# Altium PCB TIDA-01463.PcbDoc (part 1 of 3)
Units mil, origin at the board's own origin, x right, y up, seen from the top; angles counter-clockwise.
Board outline 6100 x 1060 mil, 4 copper layers (Top Layer, Signal Layer 1, Signal Layer 2, Bottom Layer), stack 61.2 mil thick; 209 components, 128 nets, 660 pads, 266 vias.
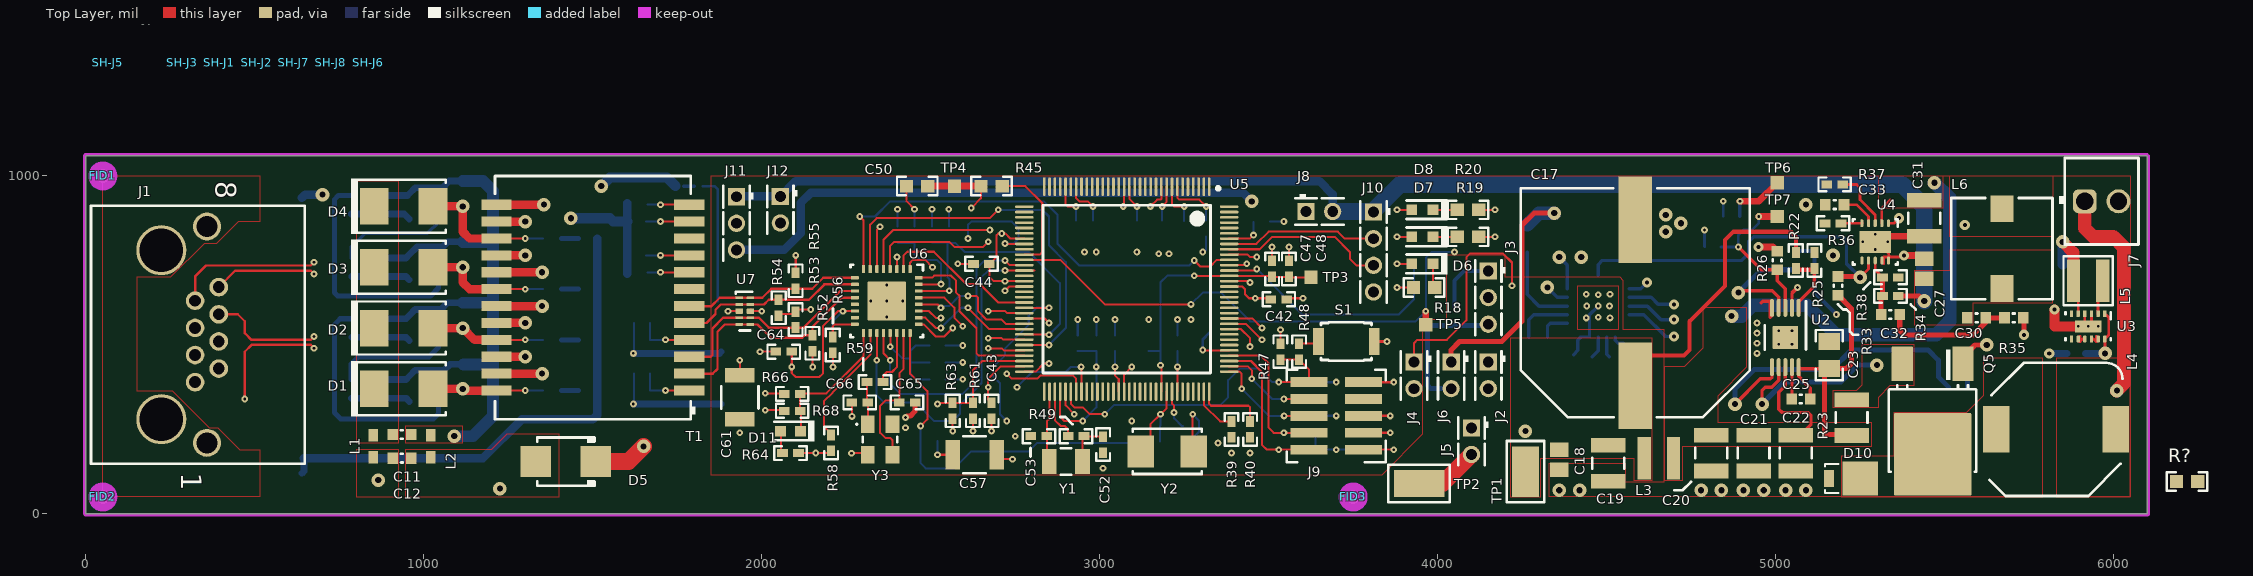
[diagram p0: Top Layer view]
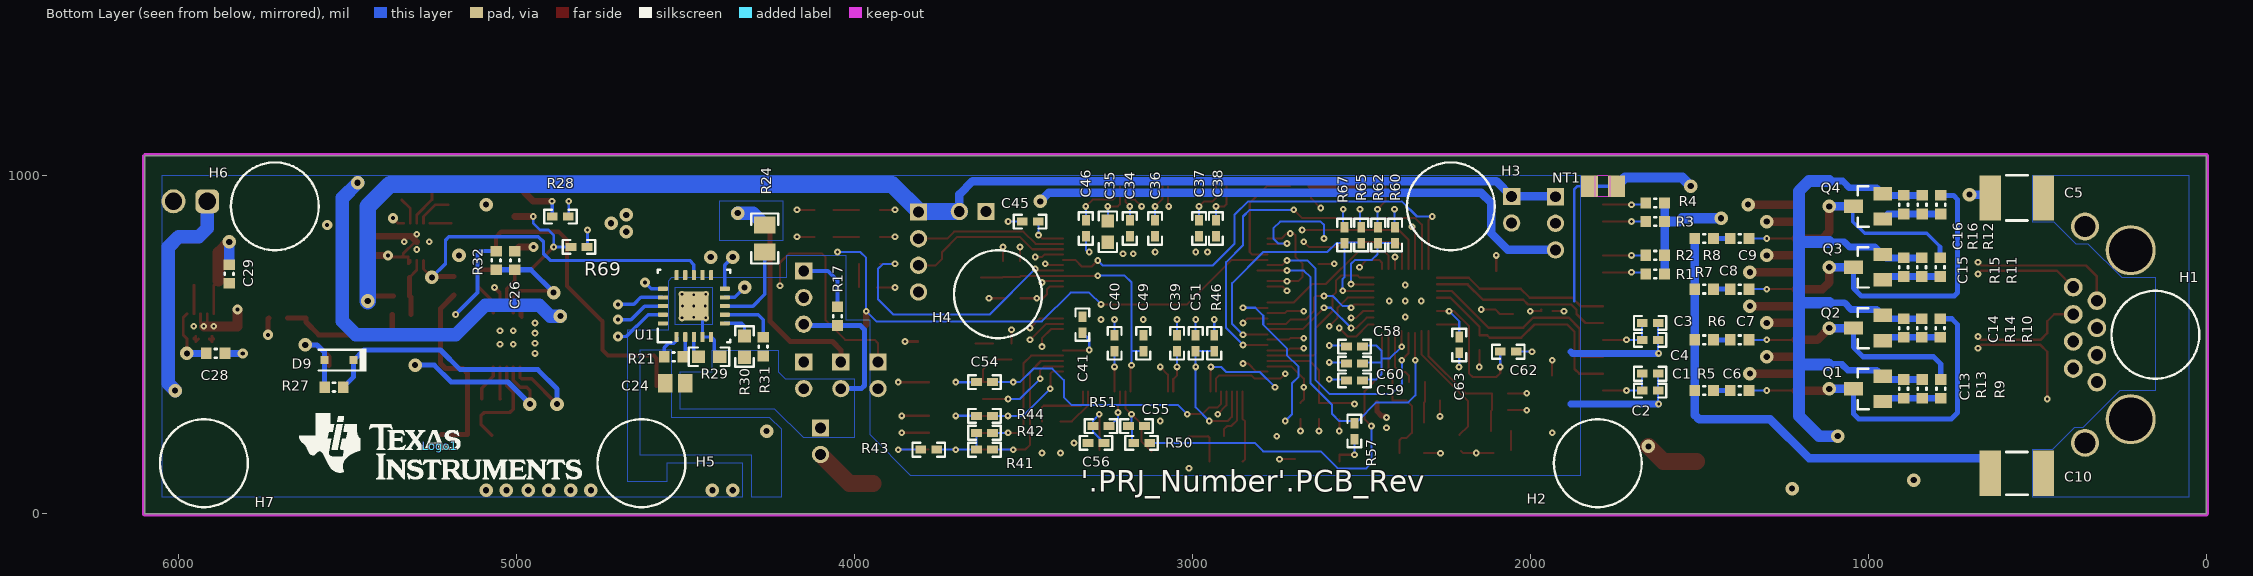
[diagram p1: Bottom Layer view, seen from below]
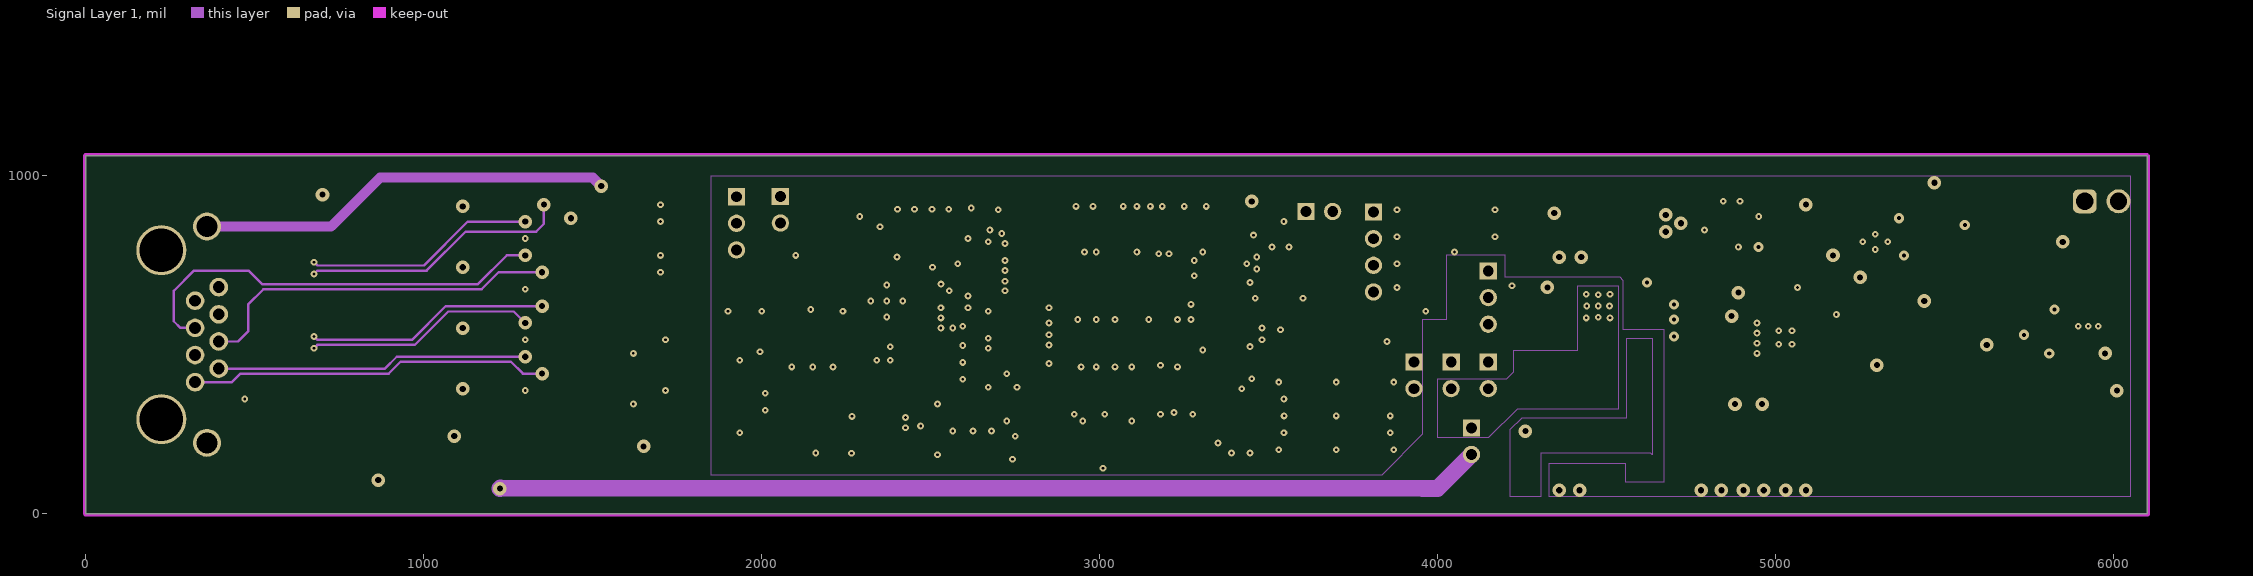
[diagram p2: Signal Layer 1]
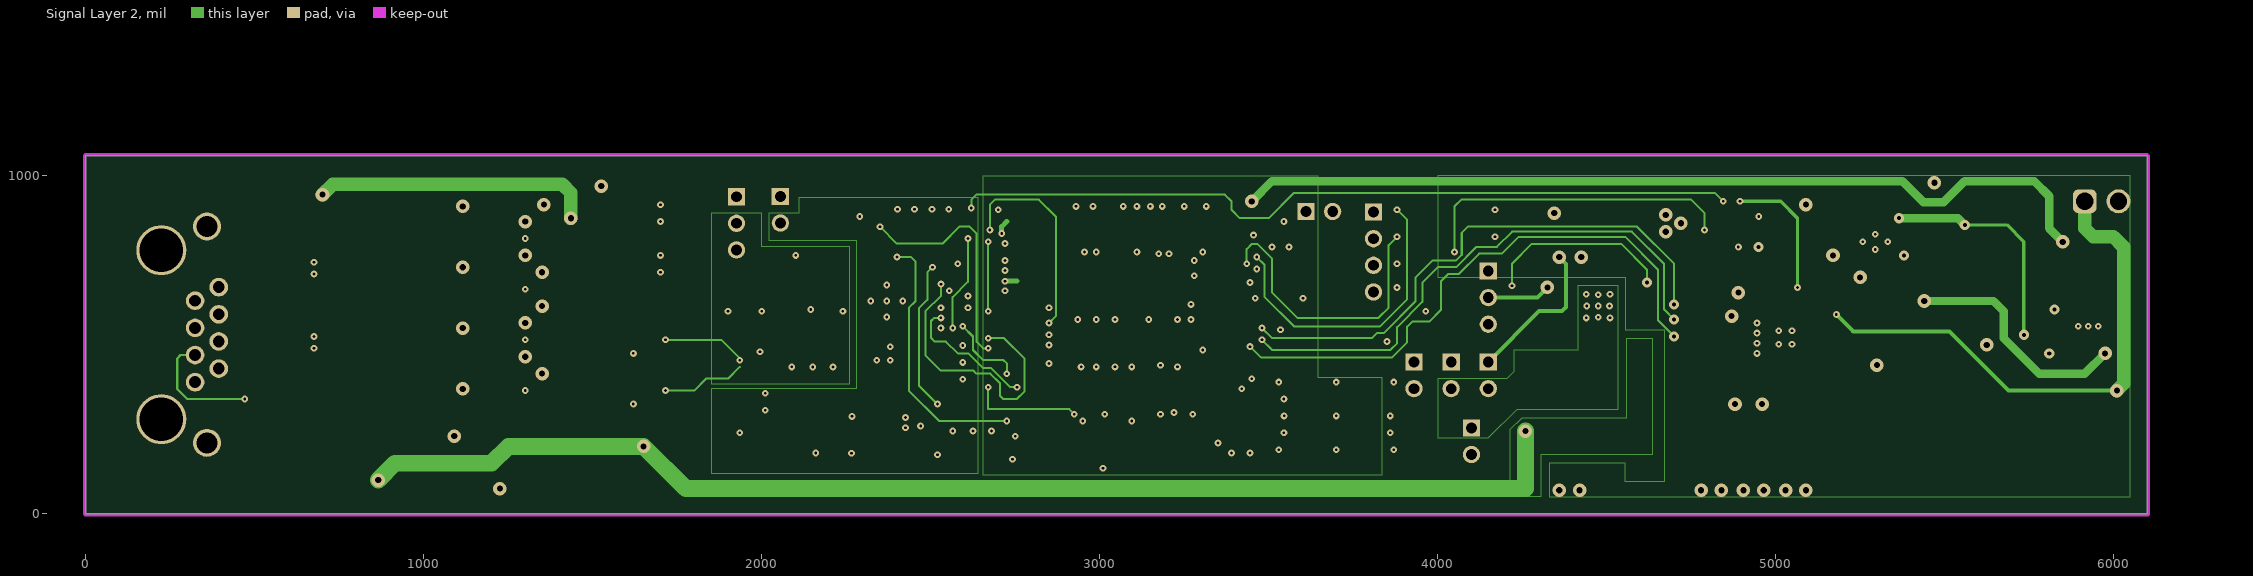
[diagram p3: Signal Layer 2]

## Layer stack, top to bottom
Top Solder: solder mask 0.4, Solder Resist, Dk 3.5
Top Layer: signal copper 1.4
Dielectric 1: core 15, FR-4, Dk 4.2
Signal Layer 1: signal copper 2.8
Dielectric 3: prepreg 22.8, Dk 4.2
Signal Layer 2: signal copper 2.8
Dielectric 2: core 15, FR-4, Dk 4.2
Bottom Layer: signal copper 1.4
Bottom Solder: solder mask 0.4, Solder Resist, Dk 3.5

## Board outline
0,0 6100,0 6100,1060 0,1060

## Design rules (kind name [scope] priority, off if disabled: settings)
AcuteAngle [All] p1: minimum=4.50000000000000E+0001 checktracksonly=FALSE
AssemblyTestPointUsage [All] p1: valid=2
BoardOutlineClearance BoardOutlineClearance_MountingHoles [OnCopper and InComponentClass('Mounting Holes')] p1: gap=40 ignorepadtopadclearanceinfootprint=FALSE
BoardOutlineClearance BoardOutlineClearance_Poly [OnCopper and IsPoly] p2: gap=25 ignorepadtopadclearanceinfootprint=FALSE
BoardOutlineClearance [OnCopper and Not InComponentClass('Logo') and not InComponentClass('FiducialMark') and not InRegion(1000,500,4000,800) and not InPoly] p3: gap=45 ignorepadtopadclearanceinfootprint=FALSE
Clearance Clearance_2 [InNamedPolygon('TOP_LAYER_NONET_P060')] p1: gap=60 ignorepadtopadclearanceinfootprint=FALSE except(0: Arc-Hole Track-Hole SMDPad-Hole THPad-Hole Via-Hole Fill-Hole Poly-Hole Region-Hole Text-Hole)
Clearance Clearance_1 [InNamedPolygon('BOTTOM_LAYER_NONET_P062')] p2: gap=60 ignorepadtopadclearanceinfootprint=FALSE except(0: Arc-Hole Track-Hole SMDPad-Hole THPad-Hole Via-Hole Fill-Hole Poly-Hole Region-Hole Text-Hole)
Clearance Clearance_Pwr2GndVia [(IsVia AND (InNet('GND') OR InNet('VCC_3P3'))) vs (IsVia AND (InNet('GND') OR InNet('VCC_3P3')))] p3: gap=5 ignorepadtopadclearanceinfootprint=FALSE except(0: Arc-Hole Track-Hole SMDPad-Hole THPad-Hole Via-Hole Fill-Hole Poly-Hole Region-Hole Text-Hole)
Clearance Clearance_Keepouts [((IsTrack Or IsArc) And Not InPoly) And IsFree and IsKeepOut vs ((IsTrack Or IsArc) And Not InPoly) And IsFree and IsKeepOut] p4: gap=0 ignorepadtopadclearanceinfootprint=FALSE
Clearance Clearance_Poly [InPolygon] p5: gap=20 ignorepadtopadclearanceinfootprint=FALSE except(0: Arc-Hole Track-Hole SMDPad-Hole THPad-Hole Via-Hole Fill-Hole Poly-Hole Region-Hole Text-Hole)
Clearance [All] p6: gap=5 ignorepadtopadclearanceinfootprint=FALSE except(0: Arc-Hole Track-Hole SMDPad-Hole THPad-Hole Via-Hole Fill-Hole Poly-Hole Region-Hole Text-Hole)
ComponentClearance ComponentClearance_MountingHoles_FiducialMarks [InComponentClass('Mounting Holes') vs InComponentClass('FiducialMark')] p1: gap=50 collisioncheckmode=3 verticalgap=10 showdistances=FALSE
ComponentClearance ComponentClearance_Shunt [InComponentClass('Header') vs InComponentClass('Shunt')] p2: gap=0 collisioncheckmode=3 verticalgap=0 showdistances=FALSE
ComponentClearance ComponentClearance_Logo [InComponentClass('Logo')] p3: gap=50 collisioncheckmode=3 verticalgap=10 showdistances=FALSE
ComponentClearance ComponentClearance_ScrewToNut [(HasFootprint('NY PMS 440 0025 PH')) vs (HasFootprint('Keystone_1902C'))] p4: gap=5 collisioncheckmode=3 verticalgap=10 showdistances=FALSE
ComponentClearance ComponentClearance_MountingHoles [InComponentClass('Mounting Holes')] p5: gap=250 collisioncheckmode=3 verticalgap=100000 showdistances=FALSE
ComponentClearance ComponentClearance_SmallPassives [HasFootprint('0201*') or HasFootprint('0402*') or HasFootprint('0508') or HasFootprint('0603*') or HasFootprint('0612') or HasFootprint('0805*') or HasFootprint('0815*') or HasFootprint('0830*') or HasFootprint('1206*') or HasFootprint('1210*') or HasFootprint('1808*') or HasFootprint('1812*') or HasFootprint('1825*') or HasFootprint('2010*') or HasFootprint('2220*') or HasFootprint('2225*') or HasFootprint('2512*') or HasFootprint('2728*') or HasFootprint('3518*') vs HasFootprint('0201*') or HasFootprint('0402*') or HasFootprint('0508') or HasFootprint('0603*') or HasFootprint('0612') or HasFootprint('0805*') or HasFootprint('0815*') or HasFootprint('0830*') or HasFootprint('1206*') or HasFootprint('1210*') or HasFootprint('1808*') or HasFootprint('1812*') or HasFootprint('1825*') or HasFootprint('2010*') or HasFootprint('2220*') or HasFootprint('2225*') or HasFootprint('2512*') or HasFootprint('2728*') or HasFootprint('3518*')] p6: gap=14.96 collisioncheckmode=3 verticalgap=10 showdistances=FALSE
ComponentClearance ComponentClearance_THtoSMT [IsThruComponent vs IsSMTComponent] p7: gap=40 collisioncheckmode=3 verticalgap=30 showdistances=FALSE
ComponentClearance ComponentClearance_THtoTH [IsThruComponent vs IsThruComponent] p8: gap=30 collisioncheckmode=3 verticalgap=30 showdistances=FALSE
ComponentClearance [All] p9: gap=30 collisioncheckmode=3 verticalgap=10 showdistances=FALSE
DiffPairsRouting [(InNet('TXD_N') OR InNet('TXD_P') OR InNet('TXDC_P') OR InNet('TXDC_N') OR InNet('RXD_N') OR InNet('RXD_P') OR InNet('RXDC_P') OR InNet('RXDC_N'))] p1: maxlimit=50 minlimit=5 mostfreqgap=5 toplayer_minwidth=6 toplayer_maxwidth=14 toplayer_prefwidth=11 midlayer1_minwidth=6 midlayer1_maxwidth=14 midlayer1_prefwidth=11 midlayer2_minwidth=6 midlayer2_maxwidth=14 midlayer2_prefwidth=11 bottomlayer_minwidth=6 bottomlayer_maxwidth=14 bottomlayer_prefwidth=11 maxuncoupledlength=1000
FabricationTestPointUsage TestPointUsage [All] p1: valid=2 allowmultiple=FALSE
FabricationTestpoint Testpoint [All] p1: side=3 testpointundercomponent=TRUE minsize=40 maxsize=100 preferedsize=60 minholesize=0 maxholesize=40 preferedholesize=32 testpointgrid=1 allowsidetop=TRUE allowsidebottom=TRUE usegrid=TRUE gridtolerance=0.01
FanoutControl Fanout_LCC [IsLCC] p1: bgadir=Out bgaviamode=Centered fanoutstyle=Auto fanoutdirection=Alternating viagrid=1 // Fanout_LCC (Default Rule)
FanoutControl Fanout_BGA [IsBGA] p2: bgadir=Out bgaviamode=Centered fanoutstyle=Auto fanoutdirection=Alternating viagrid=1 // Fanout_BGA (Default Rule)
FanoutControl Fanout_Default [All] p4: bgadir=Out bgaviamode=Centered fanoutstyle=Auto fanoutdirection=Alternating viagrid=1 // Fanout_Default (Default Rule)
FanoutControl Fanout_Small [(CompPinCount < 5)] p5: bgadir=Out bgaviamode=Centered fanoutstyle=Auto fanoutdirection=OutThenIn viagrid=1 // Fanout_Small (Default Rule)
HoleSize [All] p1: absolutevalues=TRUE maxlimit=251 minlimit=7.87 maxpercent=80.000 minpercent=20.000
MinimumAnnularRing MinimumAnnularRing_ThermalPadVias [IsVia and InAnyComponent] p1: minimumring=5
MinimumAnnularRing [All] p2: minimumring=5
MinimumSolderMaskSliver MinimumSolderMaskSliver_Logo [InComponentClass('Logo') vs InComponentClass('Logo')] p1: minsoldermaskwidth=0.7
MinimumSolderMaskSliver [All] p2: minsoldermaskwidth=3.94
PlaneConnect [All] p1: planeconnectstyle=Relief reliefexpansion=13 reliefentries=4 reliefconductorwidth=10 reliefairgap=10
PolygonConnect [All] p1: connectstyle=Direct reliefconductorwidth=10 reliefentries=4 polygonreliefangle="90 Angle" airgapwidth=10
RoutingVias ThermalPadVias [IsVia and InAnyComponent] p1: holewidth=7.87 width=19.68 viastyle="Through Hole" minholewidth=7.87 minwidth=19.68 maxholewidth=12.99 maxwidth=23.62
RoutingVias [All] p2: holewidth=8 width=20 viastyle="Through Hole" minholewidth=8 minwidth=20 maxholewidth=20 maxwidth=40
SMDNeckDown [All] p1: percent=100.000
SilkToBoardRegionClearance [Not ((IsComment or IsDesignator) And (Hide <> 'False')) and not InRegion(1000,500,4000,800)] p1:
SilkToSilkClearance SilkToSilkClearance_Pb-FreeLogo [(HasFootprint('Pb-Free_Overlay_Medium') OR HasFootprint('Pb-Free_Overlay_Small')) vs (HasFootprint('Pb-Free_Overlay_Medium') OR HasFootprint('Pb-Free_Overlay_Small'))] p1: silktosilkclearance=0
SilkToSilkClearance [All] p2: silktosilkclearance=4
SilkToSolderMaskClearance SilkToComponentPadClearance [IsPad and InAnycomponent] p1: minsilkscreentomaskgap=5 clearancetoexposedcopper=TRUE
SilkToSolderMaskClearance "Silk to Solder Mask Opening" [All] p2: minsilkscreentomaskgap=4 clearancetoexposedcopper=FALSE
SolderMaskExpansion SolderMaskExpansion_1 [All] p1: expansion=0.05
SolderMaskExpansion [All] p2: expansion=0.05
Width WidthRoom [TouchesRoom('RoomU1') OR  TouchesRoom('RoomU2')] p1: maxlimit=10 minlimit=6 preferedwidth=6
Width [All] p2: maxlimit=50 minlimit=6 preferedwidth=15 checkconnectedcopper=TRUE
15 further rules are at their usual default settings.

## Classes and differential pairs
component class Shunt: SH-J1 SH-J2 SH-J3 SH-J4 SH-J5 SH-J6 SH-J7 SH-J8
component class PMP20537_RevB_SH4: C57 C58 C59 C60 C61 C62 C63 C64 C65 C66 D11 J11 J12 R52 R53 R54 R55 R56 R57 R58 R59 R60 R61 R62 R63 R64 R65 R66 R67 R68 R71 R77 SH-J7 SH-J8 U6 U7 Y3
component class PMP20537_RevB_SH2: C17 C18 C19 C20 C21 C22 C23 C24 C25 C26 C27 C28 C29 C30 C31 C32 C33 D6 D7 D8 D9 D10 J2 J3 J4 J5 J6 J7 L3 L4 L5 L6 Q5 R17 R18 R19 R20 R21 R22 R23 R24 R25 R26 R27 R28 R29 R30 R31 R32 R33 R34 R35 R36 R37 R38 R69 R? SH-J1 SH-J2 SH-J3 SH-J4 SH-J5 TP1 TP2 TP6 TP7 U1 U2 U3 U4
component class PMP20537_RevB_SH1: C1 C2 C3 C4 C5 C6 C7 C8 C9 C10 C11 C12 C13 C14 C15 C16 D1 D2 D3 D4 D5 J1 L1 L2 NT1 Q1 Q2 Q3 Q4 R1 R2 R3 R4 R5 R6 R7 R8 R9 R10 R11 R12 R13 R14 R15 R16 T1
component class PMP20537_RevB_EVM_Hardware: !PCB1 FID1 FID2 FID3 H1 H2 H3 H4 H5 H6 H7 Logo1
component class PMP20537_RevB_SH3: C34 C35 C36 C37 C38 C39 C40 C41 C42 C43 C44 C45 C46 C47 C48 C49 C50 C51 C52 C53 C54 C55 C56 J8 J9 J10 R39 R40 R41 R42 R43 R44 R45 R46 R47 R48 R49 R50 R51 S1 SH-J6 TP3 TP4 TP5 U5 Y1 Y2
component class Header: J2 J3 J4 J5 J6 J8 J9 J10 J11 J12
component class Logo: Logo1
component class FiducialMark: FID1 FID2 FID3
differential pair TXD: +TXD_P -TXD_N
differential pair RXD: +RXD_P -RXD_N

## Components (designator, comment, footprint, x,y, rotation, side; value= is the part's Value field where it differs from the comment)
C1 "C1005X5R1A105K050BB" 0402 1645,415 r180 bottom value=1uF
C2 "885012205037" 0402 1645,365 r180 bottom value=0.1uF
C3 "C1005X5R1A105K050BB" 0402 1645,565 r180 bottom value=1uF
C4 "885012205037" 0402 1645,515 r180 bottom value=0.1uF
C5 "1812GC472KAT1A" 1812_254 560,935 r0 bottom value=4700pF
C6 "GRM188R72A103KA01D" 0603L 1380,365 r0 bottom value=0.01uF
C7 "GRM188R72A103KA01D" 0603L 1380,515 r0 bottom value=0.01uF
C8 "GRM188R72A103KA01D" 0603L 1380,665 r0 bottom value=0.01uF
C9 "GRM188R72A103KA01D" 0603L 1380,815 r0 bottom value=0.01uF
C10 "GR443QR73D102KW01L" 1812 560,120 r180 bottom value=1000pF
C11 "C1608X7R2A102K080AA" 0603L 935,235 r0 top value=1000pF
C12 "C1608X7R2A102K080AA" 0603L 935,165 r0 top value=1000pF
C13 "885012006060" 0603L 895,370 r90 bottom value=330pF
C14 "885012006060" 0603L 895,550 r90 bottom value=330pF
C15 "885012006060" 0603L 895,730 r90 bottom value=330pF
C16 "885012006060" 0603L 895,915 r90 bottom value=330pF
C17 "EEV-FK2A101M" SM_RADIAL_J16 4585,625 r90 top value=100uF
C18 "C0805C104K1RACTU" 0805L 4360,160 r270 top value=0.1uF
C19 "C1210C225K1RACTU" 1210_210L 4505,150 r270 top value=2.2uF
C20 "C1210C225K1RACTU" 1210_210L 4810,180 r270 top value=2.2uF
C21 "C1210C225K1RACTU" 1210_210L 4935,180 r270 top value=2.2uF
C22 "C1210C225K1RACTU" 1210_210L 5060,180 r270 top value=2.2uF
C23 "C0805C104K1RACTU" 0805_HV 5158.98,470 r90 top value=0.1uF
C24 "C0805C104K1RACTU" 0805L 4530,386.42 r180 bottom value=0.1uF
C25 "885012206052" 0603L 5075,340 r180 top value=1uF
C26 "06035A471JAT2A" 0603L 5005,750 r90 bottom value=470pF
C27 "GRM21BR60J226ME39L" 0805L 5440,725 r90 top value=22uF
C28 "GRM188R60J106ME47D" 0603L 5890,475 r180 bottom value=10uF
C29 "GRM188R60J106ME47D" 0603L 5850,710 r270 bottom value=10uF
C30 "885012206036" 0603L 5595,580 r0 top value=2200pF
C31 "C1210C225K1RACTU" 1210_210L 5440,875 r270 top value=2.2uF
C32 "885012206040" 0603L 5340,590 r180 top value=0.01uF
C33 "885012206091" 0603L 5175,915 r180 top value=0.022uF
C34 "C1005X5R1A105K050BB" 0402 3185,845 r270 bottom value=1uF
C35 "885012206048" 0603 3250,835 r270 bottom value=0.22uF
C36 "885012205037" 0402 3110,845 r270 bottom value=0.1uF
C37 "885012205037" 0402 2980,845 r270 bottom value=0.1uF
C38 "885012205037" 0402 2930,845 r270 bottom value=0.1uF
C39 "885012205037" 0402 3045,505 r90 bottom value=0.1uF
C40 "885012205037" 0402 3230,505 r90 bottom value=0.1uF
C41 "885012205037" 0402 3325,560 r90 bottom value=0.1uF
C42 "885012205037" 0402 3530,635 r0 top value=0.1uF
C43 "885012205037" 0402 2680,305 r270 top value=0.1uF
C44 "885012205037" 0402 2650,740 r180 top value=0.1uF
C45 "885012205037" 0402 3480,865 r0 bottom value=0.1uF
C46 "885012205031" 0402 3315,845 r270 bottom value=0.01uF
C47 "885012105013" 0402 3510,725 r90 top value=2.2uF
C48 "C1005X5R1A105K050BB" 0402 3560,725 r90 top value=1uF
C49 "885012205037" 0402 3145,505 r90 bottom value=0.1uF
C50 "885012206046" 0603 2460,970 r180 top value=0.1uF
C51 "885012205037" 0402 2990,505 r90 bottom value=0.1uF
C52 "GRM1555C1H180JA01D" 0402 3010,205 r270 top value=18pF
C53 "GRM1555C1H180JA01D" 0402 2820,230 r180 top value=18pF
C54 "885012205037" 0402 3615,390 r0 bottom value=0.1uF
C55 "GRM1555C1H220JA01D" 0402 3165,260 r180 bottom value=22pF
C56 "GRM1555C1H220JA01D" 0402 3285,210 r0 bottom value=22pF
C57 "CGA6P1X7R1E106M250AC" 1210_280 2630,175 r0 top value=10uF
C58 "885012205031" 0402 2520,495 r0 bottom value=0.01uF
C59 "885012205061" 0402 2520,395 r0 bottom value=1000pF
C60 "885012005061" 0402 2520,445 r0 bottom value=100pF
C61 "CGA6P1X7R1E106M250AC" 1210_280 1935,345 r270 top value=10uF
C62 "885012205031" 0402 2065,480 r180 bottom value=0.01uF
C63 "885012205061" 0402 2210,500 r270 bottom value=1000pF
C64 "885012005061" 0402 2065,480 r180 top value=100pF
C65 "C0402C120J3GACAUTO" 0402 2430,330 r0 top value=12pF
C66 "C0402C120J3GACAUTO" 0402 2290,330 r180 top value=12pF
D1 "B2100-13-F" SMB 940,370 r0 top value=100V
D2 "B2100-13-F" SMB 940,550 r0 top value=100V
D3 "B2100-13-F" SMB 940,730 r0 top value=100V
D4 "B2100-13-F" SMB 940,910 r0 top value=100V
D5 "824520581" DO214-AA-600W_UNI 1420,155 r180 top value=58V
D6 "150060YS75000" WL-SMCW_YELLOW 3955,740 r180 top value=Yellow
D7 "150060YS75000" WL-SMCW_YELLOW 3955,820 r180 top value=Yellow
D8 "150060YS75000" WL-SMCW_YELLOW 3955,900 r180 top value=Yellow
D9 "SD107WS-7-F" sod-323 5525,455 r0 bottom value=30V
D10 "SS2PH10-M3" DO-220AA 5205,105 r180 top value=100V
D11 "19-21UYC/S530-A4/TR8" 19-21_Yellow 2085,245 r180 top value=Yellow
FID1 "Fiducial" Fiducial10-20 50,1000 r0 top
FID2 "Fiducial" Fiducial10-20 50,50 r0 top
FID3 "Fiducial" Fiducial10-20 3750,50 r0 top
H1 "SJ5382" 3M_SJ5382 150,530 r180 bottom
H2 "SJ5382" 3M_SJ5382 1800,150 r180 bottom
H3 "SJ5382" 3M_SJ5382 2235,910 r180 bottom
H4 "SJ5382" 3M_SJ5382 3575,650 r180 bottom
H5 "SJ5382" 3M_SJ5382 4630,150 r180 bottom
H6 "SJ5382" 3M_SJ5382 5715,910 r180 bottom
H7 "SJ5382" 3M_SJ5382 5925,150 r180 bottom
J1 "1-406541-1" TEC_1-406541-1 330,530 r270 top
J2 "PTT-102-01-L-S" Samtec_PTT-102-01-x-S 4150,410 r270 top
J3 "PTT-103-01-L-S" Samtec_PTT-103-01-x-S 4150,640 r270 top
J4 "PTT-102-01-L-S" Samtec_PTT-102-01-x-S 3930,410 r270 top
J5 "PTT-102-01-L-S" Samtec_PTT-102-01-x-S 4100,215 r270 top
J6 "PTT-102-01-L-S" Samtec_PTT-102-01-x-S 4040,410 r270 top
J7 "691210910002" Wurth_691210910002 5965,925 r0 top
J8 "PTT-102-01-L-S" Samtec_PTT-102-01-x-S 3650,895 r0 top
J9 "FTSH-105-01-F-DV" Samtec_FTSH-105-01-x-DV 3700,290 r180 top
J10 "PTT-104-01-L-S" Samtec_PTT-104-01-x-S 3810,775 r270 top
J11 "PTT-103-01-L-S" Samtec_PTT-103-01-x-S 1925,860 r270 top
J12 "PTT-102-01-L-S" Samtec_PTT-102-01-x-S 2055,900 r270 top
L1 "742792641" WE-CBF_0603 850,200 r270 top value="300 ohm"
L2 "742792641" WE-CBF_0603 1020,200 r270 top value="300 ohm"
L3 "744025003" WE-TPC_2828 4655,165 r0 top value=3.3uH
L4 "7447714330" WE-PD_1050 5830,250 r0 top value=33uH
L5 "744028002" WE-TPC-T 5925,690 r180 top value=2.2uH
L6 "7447779233" WE-PD_7345_PlasticBase 5670,785 r270 top value=330uH
Logo1 "Texas Instruments" TI_Stacked_Overlay_Small 5225,200 r180 bottom
NT1 "Net-Tie" Net-Tie_0805_HV_NoOverlay 1785,970 r0 bottom net-tie
Q1 "FDN8601" SSOT-3 1000,370 r90 bottom value=100V
Q2 "FDN8601" SSOT-3 1000,550 r90 bottom value=100V
Q3 "FDN8601" SSOT-3 1000,730 r90 bottom value=100V
Q4 "FDN8601" SSOT-3 1000,910 r90 bottom value=100V
Q5 "ZXMP10A16KTC" DPAK 5465,310 r270 top value=-100V
R1 "CRCW060375R0FKEA" 0603L 1630,710 r0 bottom value=75.0
R2 "CRCW060375R0FKEA" 0603L 1630,765 r0 bottom value=75.0
R3 "CRCW060375R0FKEA" 0603L 1630,865 r0 bottom value=75.0
R4 "CRCW060375R0FKEA" 0603L 1630,920 r0 bottom value=75.0
R5 "CRCW060375R0FKEA" 0603L 1485,365 r180 bottom value=75.0
R6 "CRCW060375R0FKEA" 0603L 1485,515 r180 bottom value=75.0
R7 "CRCW060375R0FKEA" 0603L 1485,665 r180 bottom value=75.0
R8 "CRCW060375R0FKEA" 0603L 1485,815 r180 bottom value=75.0
R9 "CRCW06031M00FKEA" 0603L 785,370 r90 bottom value=1.00Meg
R10 "CRCW06031M00FKEA" 0603L 786.69,550 r90 bottom value=1.00Meg
R11 "CRCW06031M00FKEA" 0603L 786.69,730 r90 bottom value=1.00Meg
R12 "CRCW06031M00FKEA" 0603L 785,915 r90 bottom value=1.00Meg
R13 "CRCW0603232KFKEA" 0603L 840,370 r270 bottom value=232k
R14 "CRCW0603232KFKEA" 0603L 841.69,550 r270 bottom value=232k
R15 "CRCW0603232KFKEA" 0603L 841.69,730 r270 bottom value=232k
R16 "CRCW0603232KFKEA" 0603L 840,915 r270 bottom value=232k
R17 "CRCW060353K6FKEA" 0603L 4050,585 r270 bottom value=53.6k
R18 "RC0603FR-071K3L" 0603 3960,670 r0 top value=1.30k
R19 "RC0603FR-071K3L" 0603 4090,820 r180 top value=1.30k
R20 "RC0603FR-071K3L" 0603 4090,900 r180 top value=1.30k
R21 "CRCW060327K4FKEA" 0603L 4535,465 r0 bottom value=27.4k
R22 "CRCW04021M00FKED" 0402 5060,750 r90 top value=1.00Meg
R23 "MCR25JZHFLR180" 1210L 5225,285 r270 top value=0.18
R24 "ERJ-6GEYJ132V" 0805_HV 4265,815 r270 bottom value=1.3k
R25 "CRCW0402100KFKED" 0402 5115,750 r270 top value=100k
R26 "CRCW060349K9FKEA" 0603L 5005,750 r270 top value=49.9k
R27 "CRCW06030000Z0EA" 0603L 5540,375 r0 bottom value=0
R28 "ERJ-2GE0R00X" 0402 4870,880 r0 bottom value=0
R29 "RC0603FR-0763R4L" 0603 4430,465 r0 bottom value=63.4
R30 "RC0603FR-07243RL" 0603 4325,495 r90 bottom value=243
R31 "CRCW060349K9FKEA" 0603L 4270,495 r270 bottom value=49.9k
R32 "CRCW060323K2FKEA" 0603L 5060,750 r270 bottom value=23.2k
R33 "CRCW060349K9FKEA" 0603L 5185,675 r270 top value=49.9k
R34 "CRCW040210K0FKED" 0402 5340,645 r0 top value=10.0k
R35 "CRCW0603301KFKEA" 0603L 5705,580 r180 top value=301k
R36 "CRCW0402105KFKED" 0402 5170,860 r0 top value=105k
R37 "CRCW040224K9FKED" 0402 5175,975 r0 top value=24.9k
R38 "CRCW04025K76FKED" 0402 5340,700 r180 top value=5.76k
R39 "CRCW040210K0FKED" 0402 3390,250 r270 top value=10.0k
R40 "CRCW040210K0FKED" 0402 3445,250 r270 top value=10.0k
R41 "CRCW040210K0FKED" 0402 3615,190 r0 bottom value=10.0k
R42 "CRCW040210K0FKED" 0402 3615,240 r0 bottom value=10.0k
R43 "ERJ-2RKF1000X" 0402 3780,190 r180 bottom value=100
R44 "CRCW040210K0FKED" 0402 3615,290 r180 bottom value=10.0k
R45 "CRCW06031K00FKEA" 0603 2680,970 r180 top value=1.00k
R46 "CRCW040249R9FKED" 0402 2935,505 r270 bottom value=49.9
R47 "CRCW040210K0FKED" 0402 3535,480 r90 top value=10.0k
R48 "ERJ-2RKF1000X" 0402 3590,480 r270 top value=100
R49 "ERJ-2GE0R00X" 0402 2930,230 r0 top value=0
R50 "ERJ-2GE0R00X" 0402 3150,210 r0 bottom value=0
R51 "ERJ-2GE0R00X" 0402 3270,260 r180 bottom value=0
R52 "CRCW040249R9FKED" 0402 2150,505 r270 top value=49.9
R53 "CRCW040249R9FKED" 0402 2100,575 r90 top value=49.9
R54 "CRCW040249R9FKED" 0402 2050,610 r270 top value=49.9
R55 "CRCW040249R9FKED" 0402 2100,690 r90 top value=49.9
R56 "CRCW04024K87FKED" 0402 2210,500 r270 top value=4.87k
R57 "CRCW04022K21FKED" 0402 2520,245 r90 bottom value=2.21k
R58 "CRCW04023K32FKED" 0402 2205,210 r270 top value=3.32k
R59 "ERJ-2GE0R00X" 0402 2335,390 r180 top value=0
R60 "CRCW040210K0FKED" 0402 2400,825 r90 bottom value=10.0k
R61 "CRCW040210K0FKED" 0402 2625,305 r270 top value=10.0k
R62 "CRCW04022K49FKED" 0402 2450,825 r270 bottom value=2.49k
R63 "CRCW04022K49FKED" 0402 2565,305 r90 top value=2.49k
R64 "CRCW0402332RFKED" 0402 2085,180 r180 top value=332
R65 "CRCW040210K0FKED" 0402 2500,825 r90 bottom value=10.0k
R66 "CRCW04022K49FKED" 0402 2090,355 r180 top value=2.49k
R67 "CRCW04022K49FKED" 0402 2550,825 r270 bottom value=2.49k
R68 "CRCW04022K49FKED" 0402 2090,305 r0 top value=2.49k
R69 "ERJ-2GE0R00X" 0402 4815,790 r0 bottom value=0
R? "RC0603FR-071K3L" 0603 6218,96 r0 top value=1.30k
S1 "SKRKAEE010" SW_SKRKAEE010 3730,510 r180 top
SH-J1 "2SN-BK-G" 2SN-BK-G 395,1335 r90 top value=1x2
SH-J2 "2SN-BK-G" 2SN-BK-G 505,1335 r90 top value=1x2
SH-J3 "2SN-BK-G" 2SN-BK-G 285,1335 r90 top value=1x2
SH-J4 "2SN-BK-G" 2SN-BK-G 175,1335 r90 top value=1x2
SH-J5 "2SN-BK-G" 2SN-BK-G 65,1335 r90 top value=1x2
SH-J6 "2SN-BK-G" 2SN-BK-G 835,1335 r90 top value=1x2
SH-J7 "2SN-BK-G" 2SN-BK-G 615,1335 r90 top value=1x2
SH-J8 "2SN-BK-G" 2SN-BK-G 725,1335 r90 top value=1x2
T1 "7490220122" Wurth_7490220122 1500,640 r180 top value="350 uH"
TP1 "TESTPOINT" Keystone_5019 4260,125 r270 top
TP2 "TESTPOINT" Keystone_5019 3945,90 r0 top
TP3 "TESTPOINT" PAD_1MM_SQUARE 3625,700 r0 top
TP4 "TESTPOINT" PAD_1MM_SQUARE 2570,970 r0 top
TP5 "TESTPOINT" PAD_1MM_SQUARE 3965,560 r90 top
TP6 "TESTPOINT" PAD_1MM_SQUARE 5005,980 r90 top
TP7 "TESTPOINT" PAD_1MM_SQUARE 5005,880 r90 top
U1 "TPS2372-4RGWR" RGW0020B 4475,615 r90 bottom
U2 "LM3409HVMYX/NOPB" MUC10A_N 5029,522 r270 top
U3 "TPS62740DSSR" DSS0012A 5925,555 r270 top
U4 "LM5165DRCR" DRC0010J 5295,805 r270 top
U5 "TM4C1292NCPDTI3R" PDT0128A 3080,665 r270 top
U6 "DP83822IRHBR" RHB0032B 2370,630 r270 top
U7 "TPD4E05U06QDQARQ1" DQA0010A 1950,600 r0 top
Y1 "ABS07-32.768KHZ-9-T" XTAL_ABS07 2900,155 r180 top
Y2 "NX5032GA-25.000M-STD-CSK-4" NDK_NX5032GA 3200,185 r0 top
Y3 "CX3225CA25000D0HSSCC" Kyocera_CX3225CA 2350,220 r0 top

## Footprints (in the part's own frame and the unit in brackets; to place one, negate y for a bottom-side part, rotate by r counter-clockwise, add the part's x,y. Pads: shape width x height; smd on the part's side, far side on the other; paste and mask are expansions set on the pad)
2SN-BK-G [mil] "Samtec STEP model"
  round 1 on Mech3: 0(0,0)
  body extent -78,-39 79,39, height 188
3M_SJ5382 [mil] "3M BUMPON"
  silkscreen extent -130,-130 130,130, body extent -125,-125 125,125, height 75
19-21_Yellow [mm] "SMD, 2-Leads, Body 0.8x1.6mm, Pin Spacing 1.5mm"
  rect 0.8x0.8 smd: 1(-0.75,0) 2(0.75,0)
  silkscreen extent -1.8,-0.8 1.2,0.8, body extent -0.9,-0.45 0.9,0.45, height 1.01
0402 [mm] "0402 from SM-752 data"
  rect 0.8x0.6 smd: 1(-0.6,0) 2(0.6,0)
  silkscreen extent -1.22,-0.52 1.22,0.52, body extent -0.55,-0.3 0.55,0.3, height 0.6
0603 [mm] "0603 from SM-752 data"
  rect 1x0.95 smd: 1(-0.8,0) 2(0.8,0)
  silkscreen extent -1.52,-0.69 1.52,0.69, body extent -0.87,-0.47 0.87,0.47, height 1
0603L [mm] "0603 from SM-752 data"
  rect 0.8x0.85 smd: 1(-0.7,0) 2(0.7,0)
  silkscreen extent -0.07,-0.33 0.07,0.33, body extent -0.87,-0.47 0.87,0.47, height 1
0805_HV [mil] "0805 with 30mil clearance between pads"
  rect 50x63 smd: 1(-40,0) 2(40,0)
  silkscreen extent -74,-40 74,40, body extent -43,-29 43,29, height 57
0805L [mm] "0805 from SM-752 data"
  rect 1.1x1.4 smd: 1(-0.75,0) 2(0.75,0)
  body extent -1.1,-0.72 1.1,0.72, height 1.45
1210_210L [mm] "1210"
  rect 1.1x2.6 smd: 1(-1.35,0) 2(1.35,0)
  silkscreen extent -0.4,-1.2 0.4,1.2, body extent -1.7,-1.35 1.7,1.35, height 2.1
1210_280 [mm] "SMD, 2-Leads, Body 3.6x2.8mm, Height 2.8mm"
  rect 1.1x2.2 smd: 1(-1.65,0) 2(1.65,0)
  silkscreen extent -0.84,-1.4 0.84,1.4, body extent -1.8,-1.4 1.8,1.4, height 2.8
1210L [mm] "1210 from SM-752 data"
  rect 1.1x2.6 smd: 1(-1.35,0) 2(1.35,0)
  silkscreen extent -0.4,-1.2 0.4,1.2, body extent -1.7,-1.35 1.7,1.35, height 1.35
1812 [mm]
  rect 1.6x3.4 smd: 1(-2,0) 2(2,0)
  silkscreen extent -0.8,-1.6 0.8,1.6, body extent -2.4,-1.7 2.4,1.7, height 1.35
1812_254 [mm] "SMD, 2-Leads, Body 4.8x3.4mm"
  rect 1.6x3.4 smd: 1(-2,0) 2(2,0)
  silkscreen extent -0.8,-1.7 0.8,1.7, body extent -2.4,-1.7 2.4,1.7, height 2.54
DO214-AA-600W_UNI [mm] "SMD, 2-Leads, Body 4.32x3.62mm"
  rect 2.3x2.3 smd: 1(-2.25,0) 2(2.25,0)
  silkscreen extent -2.16,-1.81 2.16,1.81, body extent -2.7,-1.81 2.7,1.81, height 2.4
DO-220AA [mil] "Vishay recommended land pattern 12-Mar-12"
  rect 105.12x100 smd: 1(-46.28,0)
  rect 30x50 smd: 2(46.28,0)
  silkscreen extent 19,-43 58,43, body extent -96,-45 59,45, height 46
DPAK [mm] "D-PAK, 3-Pads, Body 6.22x6.73mm (max), TO-252AA using nominal STEP model"
  rrect6% 2.6x1.6 smd: 1(-3.4,2.28) 3(-3.4,-2.28)
  rrect2% 6.2x5.8 smd paste-2.9: 4(3.4,0)
  silkscreen extent -4.5,-3.3 4.7,3.28, body extent -3.86,-3.29 5.84,3.29, height 2.48
DQA0010A [mm] "SON, 10-Leads, Body 1x2.5mm, Pitch 0.5mm, TI Recommended"
  rrect50% 0.565x0.2 smd: 1(-0.417,1) 2(-0.417,0.5) 4(-0.417,-0.5) 5(-0.417,-1) 6(0.417,-1) 7(0.417,-0.5) 9(0.417,0.5) 10(0.417,1)
  rrect28% 0.565x0.36 on Top Paste: 3(-0.417,0) 8(0.417,0)
  rrect25% 0.565x0.4 smd paste-0.2: 3(-0.417,0) 8(0.417,0)
  silkscreen extent -0.67,-1.45 0.55,1.45, body extent -0.55,-1.3 0.55,1.3, height 0.56
DRC0010J [mm] "SON, 10-Leads, Body 3x3mm, Pitch 0.5mm, Thermal Pad 2.4x1.65mm, TI Recommended"
  rrect100% 0.6x0.24 smd: 1(-1.4,1) 2(-1.4,0.5) 3(-1.4,0) 4(-1.4,-0.5) 5(-1.4,-1) 6(1.4,-1) 7(1.4,-0.5) 8(1.4,0) 9(1.4,0.5) 10(1.4,1)
  rrect6% 1.65x2.4 smd paste-0.825: 11(0,0)
  silkscreen extent -1.7,-1.7 1.7,1.7, body extent -1.5,-1.5 1.5,1.5, height 0.77
DSS0012A [mm] "SON, 12-Leads, Body 2x3mm, Pitch 0.5mm, Thermal Pad 2x0.9mm, TI Recommended"
  rrect40% 0.5x0.25 smd: 1(-0.95,1.25) 2(-0.95,0.75) 3(-0.95,0.25) 4(-0.95,-0.25) 5(-0.95,-0.75) 6(-0.95,-1.25) 7(0.95,-1.25) 8(0.95,-0.75) 9(0.95,-0.25) 10(0.95,0.25) 11(0.95,0.75) 12(0.95,1.25)
  rrect11% 0.9x0.9 on Top Paste: 13(0,0.55) 13(0,-0.55)
  rrect11% 0.9x2 smd paste-0.45: 13(0,0)
  silkscreen extent -1.05,-1.7 1.05,1.7, body extent -1,-1.5 1,1.5, height 0.8
Fiducial10-20 [mm]
  round 1 smd mask+0.5: 1(0,0)
  Top Layer keep-out circle w1.178: c0,0 r0.5
Keystone_5019 [mm] "Test Point, Miniature, SMT"
  rect 3.8x2.03 smd: 1(0,0)
  silkscreen extent -2.31,-1.42 2.31,1.42, body extent -1.9,-1.02 1.9,1.02, height 2.29
Kyocera_CX3225CA [mm] "SMD, 4-Leads, Body 3.2x2.5mm"
  rect 1.05x1.3 smd: 1(-0.925,1.15) 2(-0.925,-1.15) 3(0.925,-1.15) 4(0.925,1.15)
  silkscreen extent -1.81,-0.2 1.3,1.21, body extent -1.3,-1.65 1.3,1.65, height 0.91
MUC10A_N [mm] "TSSOP, 10-Leads, Body 3x3mm, Pitch 0.5mm, Exposed Pad, IPC Medium Density"
  rrect100% 1.35x0.3 smd: 1(-2.225,1) 2(-2.225,0.5) 3(-2.225,0) 4(-2.225,-0.5) 5(-2.225,-1) 6(2.225,-1) 7(2.225,-0.5) 8(2.225,0) 9(2.225,0.5) 10(2.225,1)
  rrect6% 1.73x1.9 smd: 11(0,0)
  silkscreen extent -2.73,-1.55 0.9,1.55, body extent -2.45,-1.5 2.45,1.5, height 0.96
NDK_NX5032GA [mm] "SMD, 2-Leads Body 5x3.2mm"
  rect 2x2.4 smd: 1(-2,0) 2(2,0)
  silkscreen extent -2.6,-1.7 2.6,1.7, body extent -2.6,-1.7 2.6,1.7, height 1.5
Net-Tie_0805_HV_NoOverlay [mil] "0805_HV pads tied by 10mil copper trace which can be cut.  An 0805 part can be placed on pads."
  rect 50x63 smd paste-25: 1(-40,0) 2(40,0)
  Top Layer lines w10: -16,0 16,0
  Top Layer keep-out lines w1: -22,30.91 -22,-30.91 ; -14.96,30.91 14.96,30.91 ; -14.96,-30.91 14.96,-30.91 ; 22,30.91 22,-30.91
PAD_1MM_SQUARE [mm]
  rect 1x1 smd: 1(0,0)
PDT0128A [mm] "Thin QFP, 128-Leads, Body 14x14mm, Pitch 0.4mm"
  oval 1.4x0.2 smd: 1(-7.7,6.2) 2(-7.7,5.8) 3(-7.7,5.4) 4(-7.7,5) 5(-7.7,4.6) 6(-7.7,4.2) 7(-7.7,3.8) 8(-7.7,3.4) 9(-7.7,3) 10(-7.7,2.6) 11(-7.7,2.2) 12(-7.7,1.8) 13(-7.7,1.4) 14(-7.7,1) 15(-7.7,0.6) 16(-7.7,0.2) 17(-7.7,-0.2) 18(-7.7,-0.6) 19(-7.7,-1) 20(-7.7,-1.4) 21(-7.7,-1.8) 22(-7.7,-2.2) 23(-7.7,-2.6) 24(-7.7,-3) 25(-7.7,-3.4) 26(-7.7,-3.8) 27(-7.7,-4.2) 28(-7.7,-4.6) 29(-7.7,-5) 30(-7.7,-5.4) 31(-7.7,-5.8) 32(-7.7,-6.2) 65(7.7,-6.2) 66(7.7,-5.8) 67(7.7,-5.4) 68(7.7,-5) 69(7.7,-4.6) 70(7.7,-4.2) 71(7.7,-3.8) 72(7.7,-3.4) 73(7.7,-3) 74(7.7,-2.6) 75(7.7,-2.2) 76(7.7,-1.8) 77(7.7,-1.4) 78(7.7,-1) 79(7.7,-0.6) 80(7.7,-0.2) 81(7.7,0.2) 82(7.7,0.6) 83(7.7,1) 84(7.7,1.4) 85(7.7,1.8) 86(7.7,2.2) 87(7.7,2.6) 88(7.7,3) 89(7.7,3.4) 90(7.7,3.8) 91(7.7,4.2) 92(7.7,4.6) 93(7.7,5) 94(7.7,5.4) 95(7.7,5.8) 96(7.7,6.2)
  oval 0.2x1.4 smd: 33(-6.2,-7.7) 34(-5.8,-7.7) 35(-5.4,-7.7) 36(-5,-7.7) 37(-4.6,-7.7) 38(-4.2,-7.7) 39(-3.8,-7.7) 40(-3.4,-7.7) 41(-3,-7.7) 42(-2.6,-7.7) 43(-2.2,-7.7) 44(-1.8,-7.7) 45(-1.4,-7.7) 46(-1,-7.7) 47(-0.6,-7.7) 48(-0.2,-7.7) 49(0.2,-7.7) 50(0.6,-7.7) 51(1,-7.7) 52(1.4,-7.7) 53(1.8,-7.7) 54(2.2,-7.7) 55(2.6,-7.7) 56(3,-7.7) 57(3.4,-7.7) 58(3.8,-7.7) 59(4.2,-7.7) 60(4.6,-7.7) 61(5,-7.7) 62(5.4,-7.7) 63(5.8,-7.7) 64(6.2,-7.7) 97(6.2,7.7) 98(5.8,7.7) 99(5.4,7.7) 100(5,7.7) 101(4.6,7.7) 102(4.2,7.7) 103(3.8,7.7) 104(3.4,7.7) 105(3,7.7) 106(2.6,7.7) 107(2.2,7.7) 108(1.8,7.7) 109(1.4,7.7) 110(1,7.7) 111(0.6,7.7) 112(0.2,7.7) 113(-0.2,7.7) 114(-0.6,7.7) 115(-1,7.7) 116(-1.4,7.7) 117(-1.8,7.7) 118(-2.2,7.7) 119(-2.6,7.7) 120(-3,7.7) 121(-3.4,7.7) 122(-3.8,7.7) 123(-4.2,7.7) 124(-4.6,7.7) 125(-5,7.7) 126(-5.4,7.7) 127(-5.8,7.7) 128(-6.2,7.7)
  silkscreen extent -7.7,-6.3 6.3,7, body extent -8,-8 8,8, height 1.07
RGW0020B [mm] "QFN, 20-Leads, Body 5x5mm, Pitch 0.65mm, Thermal Pad 2.2x2.2mm, TI Recommended"
  rrect32% 0.75x0.31 smd: 1(-2.325,1.3) 2(-2.325,0.65) 3(-2.325,0) 4(-2.325,-0.65) 5(-2.325,-1.3) 11(2.325,-1.3) 12(2.325,-0.65) 13(2.325,0) 14(2.325,0.65) 15(2.325,1.3)
  rrect32% 0.31x0.75 smd: 6(-1.3,-2.325) 7(-0.65,-2.325) 8(0,-2.325) 9(0.65,-2.325) 10(1.3,-2.325) 16(1.3,2.325) 17(0.65,2.325) 18(0,2.325) 19(-0.65,2.325) 20(-1.3,2.325)
  rrect10% 0.98x0.98 on Bottom Paste: 21(-0.59,-0.59) 21(-0.59,0.59) 21(0.59,-0.59) 21(0.59,0.59)
  rrect5% 2.2x2.2 smd paste-1.1: 21(0,0)
  silkscreen extent -2.73,-2.73 2.73,2.73, body extent -2.5,-2.5 2.5,2.5, height 0.97
RHB0032B [mm] "QFN, 32-Leads, Body 5x5mm, Pitch 0.5mm, Thermal Pad 2.9x2.9mm"
  rrect40% 0.6x0.25 smd: 1(-2.4,1.75) 2(-2.4,1.25) 3(-2.4,0.75) 4(-2.4,0.25) 5(-2.4,-0.25) 6(-2.4,-0.75) 7(-2.4,-1.25) 8(-2.4,-1.75) 17(2.4,-1.75) 18(2.4,-1.25) 19(2.4,-0.75) 20(2.4,-0.25) 21(2.4,0.25) 22(2.4,0.75) 23(2.4,1.25) 24(2.4,1.75)
  rrect40% 0.25x0.6 smd: 9(-1.75,-2.4) 10(-1.25,-2.4) 11(-0.75,-2.4) 12(-0.25,-2.4) 13(0.25,-2.4) 14(0.75,-2.4) 15(1.25,-2.4) 16(1.75,-2.4) 25(1.75,2.4) 26(1.25,2.4) 27(0.75,2.4) 28(0.25,2.4) 29(-0.25,2.4) 30(-0.75,2.4) 31(-1.25,2.4) 32(-1.75,2.4)
  rrect8% 1.27x1.27 on Top Paste: 33(-0.735,0.735) 33(-0.735,-0.735) 33(0.735,0.735) 33(0.735,-0.735)
  rrect3% 2.9x2.9 smd paste-1.725: 33(0,0)
  silkscreen extent -2.72,-2.73 2.72,2.73, body extent -2.57,-2.57 2.58,2.58, height 1.01
Samtec_FTSH-105-01-x-DV [mm] "Header, 1.27mm, 5x2, SMT"
  rect 2.79x0.74 smd: 1(-2.035,2.54) 2(2.035,2.54) 3(-2.035,1.27) 4(2.035,1.27) 5(-2.035,0) 6(2.035,0) 7(-2.035,-1.27) 8(2.035,-1.27) 9(-2.035,-2.54) 10(2.035,-2.54)
  silkscreen extent -3.73,-3.48 3.73,3.48, body extent -2.92,-3.17 2.92,3.18, height 5.98
Samtec_PTT-102-01-x-S [mm] "Header, 2mm, 2x1, TH"
  rect 1.3x1.3 hole 0.81: 1(-1,0)
  round 1.3 hole 0.81: 2(1,0)
  silkscreen extent -1.81,-0.99 1.81,1.3, body extent -2,-0.99 2,0.99, height 4.7
Samtec_PTT-103-01-x-S [mm] "Header, 2mm, 3x1, TH"
  rect 1.3x1.3 hole 0.81: 1(-2,0)
  round 1.3 hole 0.81: 2(0,0) 3(2,0)
  silkscreen extent -2.81,-0.99 2.81,1.3, body extent -3,-0.99 3,0.99, height 4.7
Samtec_PTT-104-01-x-S [mm] "Header, 2mm, 4x1, TH"
  rect 1.3x1.3 hole 0.81: 1(-3,0)
  round 1.3 hole 0.81: 2(-1,0) 3(1,0) 4(3,0)
  silkscreen extent -3.81,-0.99 3.81,1.3, body extent -4,-0.99 4,0.99, height 4.7
SM_RADIAL_J16 [mm] "16 x 16.5mm:  Panasonic J16"
  rect 6.5x2.5 smd: 1(-6.25,0) 2(6.25,0)
  silkscreen extent -8.6,-8.6 8.6,8.6, body extent -8.6,-8.6 8.6,8.6, height 17
SMB [mil] "Molded Diode, 2-Leads, Body 5.4x3.6mm, IPC Medium Density, based on OnSemi component dimensions"
  rect 85x107.99 smd: 1(-87.01,0) 2(87.01,0)
  silkscreen extent -155,-82 125,82, body extent -106,-71 106,71, height 91
sod-323 [mm] "NXP recommended land pattern"
  rect 0.6x0.6 smd paste-0.05: 1(-1.1,0) 2(1.1,0)
  silkscreen extent -2.06,-0.86 1.53,0.86, body extent -1.3,-0.67 1.3,0.68, height 1.1
SSOT-3 [mm] "SuperSOT-3"
  rect 1x1.4 smd: 1(-0.95,-1.1) 2(0.95,-1.1) 3(0,1.1)
  silkscreen extent -1.53,-0.05 1.5,0.77, body extent -1.52,-0.76 1.52,0.76, height 1.12
SW_SKRKAEE010 [mm] "Alps recommended land pattern"
  rect 0.8x2 smd: 1(-2.1,0) 2(2.1,0)
  silkscreen extent -1.9,-1.44 1.92,1.44, body extent -2.4,-1.45 2.4,1.45, height 1.96
TEC_1-406541-1 [mm] "TE Connectivity"
  round 1.4 hole 0.89: 1(3.56,-0.18) 2(2.54,1.6) 3(1.52,-0.18) 4(0.5,1.6) 5(-0.52,-0.18) 6(-1.54,1.6) 7(-2.56,-0.18) 8(-3.58,1.6)
  round 2.1 hole 1.57: 9(8.12,0.71) 10(-8.14,0.71)
  round 3.759 hole 3.251: 11(6.34,-2.72) 12(-6.36,-2.72)
  silkscreen extent -9.69,-8 9.69,8.06, body extent -9.33,-8 9.31,7.75, height 14.8
TI_Stacked_Overlay_Small [mil]
  silkscreen extent -418,-98 418,98
WE-CBF_0603 [mm] "WE_SMT-0603"
  rect 0.95x0.7 smd: 1(-0.825,0) 2(0.825,0)
  body extent -0.9,-0.5 0.9,0.5, height 1
WE-PD_1050 [mm] "WERTH"
  rect 2x3.5 smd: 1(-4.5,0) 2(4.5,0)
  silkscreen extent -5,-5 5,5, body extent -5,-5 5,5, height 4.75
WE-PD_7345_PlasticBase [mm] "SMD Inductor, 2-Leads, Body 7,3x7,3mm"
  rect 2x1.7 smd: 1(-3,0) 2(3,0)
  silkscreen extent -3.8,-3.8 3.8,3.8, body extent -3.65,-3.65 3.65,3.65, height 4.09
WE-TPC-T [mm] "Wurth Elektronik recommended land pattern"
  rect 1x3.2 smd: 1(-1.1,0) 2(1.1,0)
  silkscreen extent -1.85,-1.85 1.85,1.85, body extent -1.5,-1.5 1.5,1.5, height 1.2
WE-TPC_2828 [mm] "WURTH"
  rect 1x3.2 smd: 1(-1.1,0) 2(1.1,0)
  body extent -1.5,-1.5 1.5,1.5, height 3
WL-SMCW_YELLOW [mm] "WURTH"
  rect 0.8x0.8 smd: 1(-0.8,0) 2(0.8,0)
  silkscreen extent -1.9,-0.8 1.2,0.8, body extent -0.85,-0.45 0.85,0.45, height 0.8
Wurth_7490220122 [mm] "SMD, 24-Leads, Body 14.7x18.29mm"
  rect 2.29x0.76 smd: 1(-7.24,6.985) 2(-7.24,5.715) 3(-7.24,4.445) 4(-7.24,3.175) 5(-7.24,1.905) 6(-7.24,0.635) 7(-7.24,-0.635) 8(-7.24,-1.905) 9(-7.24,-3.175) 10(-7.24,-4.445) 11(-7.24,-5.715) 12(-7.24,-6.985) 13(7.24,-6.985) 14(7.24,-5.715) 15(7.24,-4.445) 16(7.24,-3.175) 17(7.24,-1.905) 18(7.24,-0.635) 19(7.24,0.635) 20(7.24,1.905) 21(7.24,3.175) 22(7.24,4.445) 23(7.24,5.715) 24(7.24,6.985)
  silkscreen extent -7.7,-9.15 7.35,9.15, body extent -7.35,-9.15 7.35,9.15, height 8.81
Wurth_691210910002 [mm] "Receptacle, 2.54mm, 2x1, R/A, TH"
  rrect50% 1.8x1.8 hole 1.3: 1(-1.27,0)
  round 1.8 hole 1.3: 2(1.27,0)
  silkscreen extent -3.2,-3.25 2.77,3.25, body extent -2.77,-3.25 2.77,3.25, height 8.85
XTAL_ABS07 [mm] "ABRACON"
  rect 1.1x1.9 smd: 1(-1.25,0) 2(1.25,0)
  silkscreen extent -0.4,-1 0.4,1, body extent -1.65,-0.8 1.65,0.8, height 0.9

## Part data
C1 C3 C34 C48: "CAP, CERM, 1 µF, 10 V, +/- 10%, X5R, 0402", Cap_Case=0402, Manufacturer=TDK, Supplier Part Number 1=445-4114-1-ND, TempCo=X5R, Tolerance_%=10, Value1=Unknown, Value2=10V, ValueDisplayed=1µF
C2 C4 C36 C37 C38 C39 C40 C41 C42 C43 C44 C45 C49 C51 C54: "CAP, CERM, 0.1 µF, 16 V, +/- 10%, X7R, 0402", Cap_Case=0402, Manufacturer="Wurth Elektronik", Supplier Part Number 1=732-7532-1-ND, TempCo=X7R, Tolerance_%=10, Value1=Unknown, Value2=16V, ValueDisplayed=0.1µF
C5: "CAP, CERM, 4700 pF, 2000 V, +/- 10%, X7R, 1812", Cap_Case=1812, Manufacturer=AVX, Supplier Part Number 1=478-3003-1-ND, TempCo=X7R, Tolerance_%=10, Value1=Unknown, Value2=2000V, ValueDisplayed=4700pF
C6 C7 C8 C9: "CAP, CERM, 0.01 µF, 100 V, +/- 10%, X7R, 0603", Cap_Case=0603, Manufacturer=MuRata, Supplier Part Number 1=GRM188R72A103KA01D-ND, TempCo=X7R, Tolerance_%=10, Value1=Unknown, Value2=100V, ValueDisplayed=0.01µF
C10: "CAP, CERM, 1000 pF, 2000 V,+/- 10%, X7R, 1812", Cap_Case=1812, Manufacturer=MuRata, TempCo=X7R, Tolerance_%=10, Value2=2000V, ValueDisplayed=1000pF
C11 C12: "CAP, CERM, 1000 pF, 100 V, +/- 10%, X7R, 0603", Cap_Case=0603, Manufacturer=TDK, Supplier Part Number 1=445-1298-1-ND, TempCo=X7R, Tolerance_%=10, Value1=Unknown, Value2=100V, ValueDisplayed=1000pF
C13 C14 C15 C16: "CAP, CERM, 330 pF, 50 V, +/- 5%, C0G/NP0, 0603", Cap_Case=0603, Manufacturer="Wurth Elektronik", Supplier Part Number 1=710-885012006060, TempCo=C0G/NP0, Tolerance_%=5, Value1=Unknown, Value2=50V, ValueDisplayed=330pF
C17: "CAP, AL, 100 µF, 100 V, +/- 20%, 0.17 ohm, SMD", Cap_Case=J16, Manufacturer=Panasonic, Supplier Part Number 1=PCE3504CT-ND, Tolerance_%=20, Value1="0.17 ohm", Value2=100V, ValueDisplayed=100µF
C18 C23 C24: "CAP, CERM, 0.1 µF, 100 V, +/- 10%, X7R, 0805", Cap_Case=0805, Manufacturer=Kemet, Supplier Part Number 1=399-3486-1-ND, TempCo=X7R, Tolerance_%=10, Value1="0.064 ohm", Value2=100V, ValueDisplayed=0.1µF
C19 C20 C21 C22 C31: "CAP, CERM, 2.2 µF, 100 V, +/- 10%, X7R, 1210", Cap_Case=1210, Manufacturer=Kemet, Supplier Part Number 1=399-5511-2-ND, TempCo=X7R, Tolerance_%=10, Value1=Unknown, Value2=100V, ValueDisplayed=2.2µF
C25: "CAP, CERM, 1 µF, 16 V, +/- 10%, X7R, 0603", Cap_Case=0603, Manufacturer="Wurth Elektronik", Supplier Part Number 1=710-885012206052, TempCo=X7R, Tolerance_%=10, Value1=Unknown, Value2=16V, ValueDisplayed=1µF
C26: "CAP, CERM, 470 pF, 50 V, +/- 5%, C0G/NP0, 0603", Cap_Case=0603, Manufacturer=AVX, Supplier Part Number 1=478-1183-1-ND, TempCo=C0G/NP0, Tolerance_%=5, Value1="0.063 ohm", Value2=50V, ValueDisplayed=470pF
C27: "CAP, CERM, 22 µF, 6.3 V, +/- 20%, X5R, 0805", Cap_Case=0805, Manufacturer=MuRata, Supplier Part Number 1=81-GRM21R60J226ME39L, TempCo=X5R, Tolerance_%=20, Value1="0.009 ohm", Value2=6.3V, ValueDisplayed=22µF
C28 C29: "CAP, CERM, 10 µF, 6.3 V, +/- 20%, X5R, 0603", Cap_Case=0603, Manufacturer=MuRata, Supplier Part Number 1=490-3896-1-ND, TempCo=X5R, Tolerance_%=20, Value1="0.009 ohm", Value2=6.3V, ValueDisplayed=10µF
C30: "CAP, CERM, 2200 pF, 16 V, +/- 10%, X7R, 0603", Cap_Case=0603, Manufacturer="Wurth Elektronik", Supplier Part Number 1=710-885012206036, TempCo=X7R, Tolerance_%=10, Value1=Unknown, Value2=16V, ValueDisplayed=2200pF
C32: "CAP, CERM, 0.01 µF, 16 V, +/- 10%, X7R, 0603", Cap_Case=0603, Manufacturer="Wurth Elektronik", Supplier Part Number 1=732-7959-1-ND, TempCo=X7R, Tolerance_%=10, Value1=Unknown, Value2=16V, ValueDisplayed=0.01µF
C33: "CAP, CERM, 0.022 µF, 50 V, +/- 10%, X7R, 0603", Cap_Case=0603, Manufacturer="Wurth Elektronik", TempCo=X7R, Tolerance_%=10, Value1=Unknown, Value2=50V, ValueDisplayed=0.022µF
C35: "CAP, CERM, 0.22 µF, 16 V, +/- 10%, X7R, 0603", Cap_Case=0603, Manufacturer="Wurth Elektronik", Supplier Part Number 1=710-885012206048, TempCo=X7R, Tolerance_%=10, Value1=Unknown, Value2=16V, ValueDisplayed=0.22µF
C46 C58 C62: "CAP, CERM, 0.01 µF, 16 V, +/- 10%, X7R, 0402", Cap_Case=0402, Manufacturer="Wurth Elektronik", Supplier Part Number 1=710-885012205031, TempCo=X7R, Tolerance_%=10, Value1=Unknown, Value2=16V, ValueDisplayed=0.01µF
C47: "CAP, CERM, 2.2 µF, 10 V, +/- 20%, X5R, 0402", Cap_Case=0402, Manufacturer="Wurth Elektronik", Supplier Part Number 1=710-885012105013, TempCo=X5R, Tolerance_%=20, Value1=Unknown, Value2=10V, ValueDisplayed=2.2µF
C50: "CAP, CERM, 0.1 µF, 16 V, +/- 10%, X7R, 0603", Cap_Case=0603, Manufacturer="Wurth Elektronik", Supplier Part Number 1=710-885012206046, TempCo=X7R, Tolerance_%=10, Value1=Unknown, Value2=16V, ValueDisplayed=0.1µF
C52 C53: "CAP, CERM, 18 pF, 50 V, +/- 5%, C0G/NP0, 0402", Cap_Case=0402, Manufacturer=MuRata, Supplier Part Number 1=81-GRM1555C1H180JA1D, TempCo=C0G/NP0, Tolerance_%=5, Value1=Unknown, Value2=50V, ValueDisplayed=18pF
C55 C56: "CAP, CERM, 22 pF, 50 V, +/- 5%, C0G/NP0, 0402", Cap_Case=0402, Manufacturer=MuRata, Supplier Part Number 1=81-GRM1555C1H220JA1D, TempCo=C0G/NP0, Tolerance_%=5, Value1=Unknown, Value2=50V, ValueDisplayed=22pF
